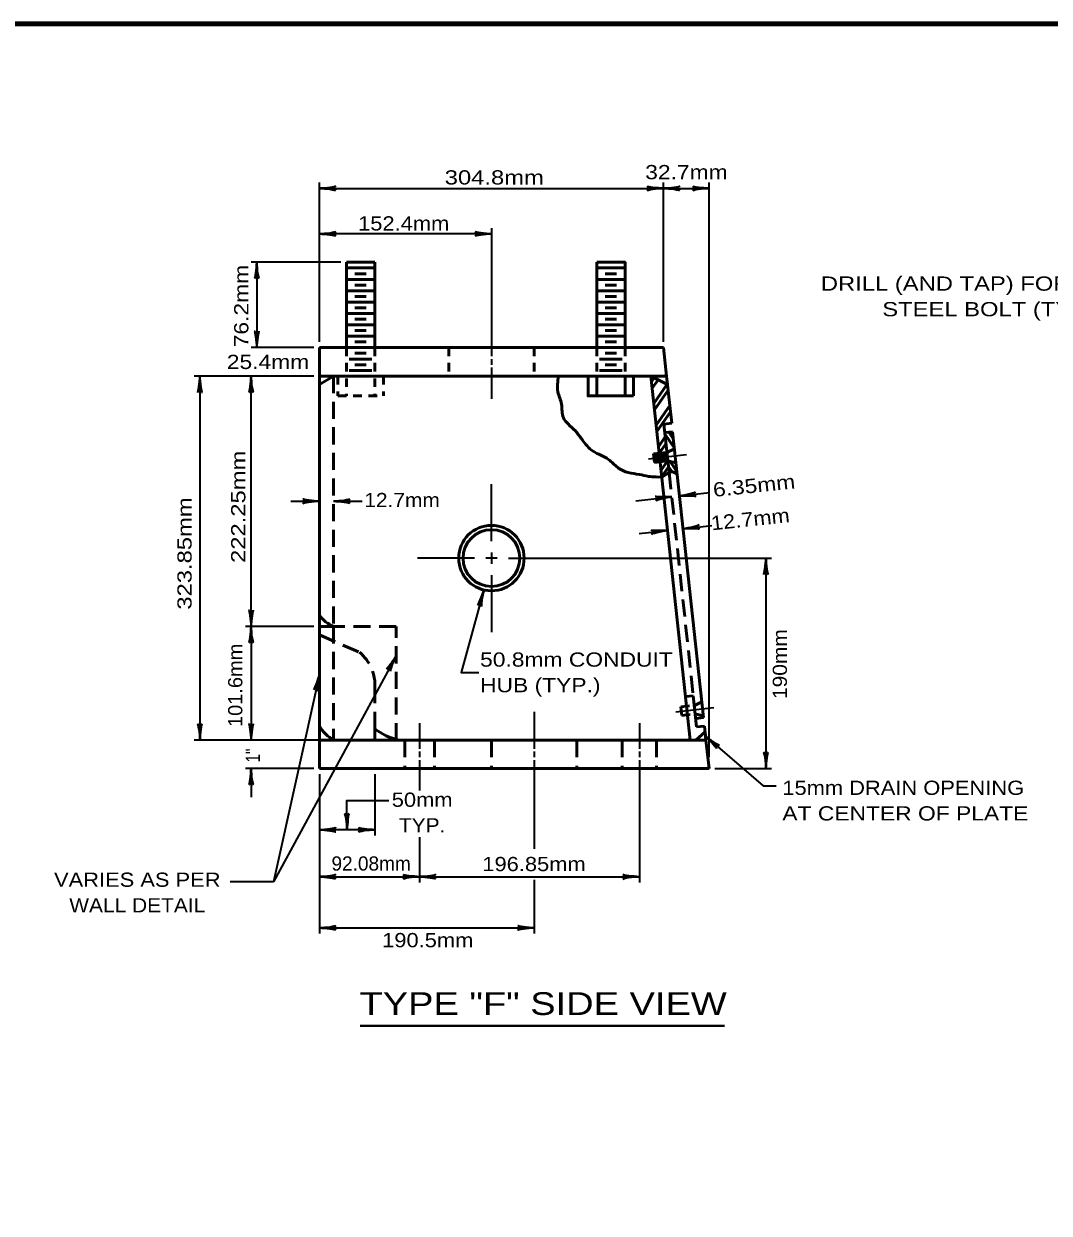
# Model space of a CAD drawing. Extents: x -40 to 816, y -10 to 535.
# Drawn here: x 186.5 to 402.8, y 277.2 to 528.1 of the extents above; entities that cross this region are included whole.
import ezdxf
from ezdxf.enums import TextEntityAlignment as Align

# ---------------------------------------------------------------- set-up
doc = ezdxf.new("R2010")
doc.units = 0
doc.header["$LTSCALE"] = 1.2
doc.linetypes.add('MEDIUM_DASHED', pattern=[4.5, 3, -1.5])
doc.linetypes.add('SHORT_DASHED', pattern=[2.7, 1.5, -1.2])
doc.layers.add('1', color=7, linetype='Continuous', lineweight=53)

msp = doc.modelspace()

# ---------------------------------------------------------------- linework, layer by layer
at = {"layer": '1', "lineweight": 35}
for p, q in [((248.805, 461.005), (248.805, 494.605)), ((321.405, 461.005), (321.405, 494.605)), ((331.005, 373.405), (331.005, 494.605)), ((285.105, 485.005), (285.105, 458.005)), ((285.105, 483.805), (248.805, 483.805)), ((253.305, 477.805), (234.405, 477.805)), ((235.605, 477.805), (235.605, 459.805)), ((247.605, 459.805), (234.405, 459.805)), ((285.105, 457.405), (285.105, 456.205)), ((285.105, 455.605), (285.105, 449.005)), ((247.605, 453.805), (222.405, 453.805)), ((223.605, 453.805), (223.605, 377.005)), ((234.405, 401.005), (234.405, 453.805)), ((318.205, 436.369), (326.258, 437.239)), ((285.105, 419.005), (285.105, 431.005)), ((324.787, 428.521), (331.207, 429.215)), ((242.805, 427.405), (248.805, 427.405)), ((251.805, 427.405), (257.805, 427.405)), ((315.541, 427.522), (323.146, 428.344)), ((325.534, 421.606), (331.616, 422.263)), ((316.288, 420.606), (322.253, 421.251)), ((285.105, 416.605), (285.105, 414.205)), ((281.505, 415.405), (269.505, 415.405)), ((286.305, 415.405), (283.905, 415.405)), ((288.705, 415.405), (344.204, 415.405)), ((343.005, 415.405), (343.005, 371.005)), ((285.105, 411.805), (285.105, 399.805)), ((247.605, 401.005), (233.205, 401.005)), ((234.405, 401.005), (234.405, 377.005)), ((265.005, 394.816), (239.107, 347.123)), ((248.805, 390.857), (239.107, 347.123)), ((323.979, 383.005), (332.032, 383.875)), ((294.105, 383.005), (294.105, 375.205)), ((269.955, 380.605), (269.955, 375.205)), ((316.305, 380.605), (316.305, 375.205)), ((248.805, 377.005), (222.405, 377.005)), ((269.955, 374.605), (269.955, 373.405)), ((294.105, 374.605), (294.105, 373.405)), ((316.305, 374.605), (316.305, 373.405)), ((269.955, 372.805), (269.955, 366.405)), ((294.105, 372.805), (294.105, 354.088)), ((316.305, 372.805), (316.305, 347.005)), ((247.605, 371.005), (233.205, 371.005)), ((234.405, 371.005), (234.405, 365.005)), ((248.805, 369.805), (248.805, 336.205)), ((260.505, 369.805), (260.505, 356.9)), ((332.205, 371.005), (344.204, 371.005)), ((260.505, 358.1), (248.805, 358.1)), ((269.955, 356.548), (269.955, 347.005)), ((239.107, 347.123), (230.022, 347.123)), ((294.105, 347.525), (294.105, 336.205)), ((248.805, 337.405), (294.105, 337.405))]:
    msp.add_line(p, q, dxfattribs=at)
at = {"layer": '1'}
for p, q in [((254.505, 459.805), (254.505, 477.805)), ((254.505, 477.805), (260.505, 477.805)), ((260.505, 459.805), (260.505, 477.805)), ((307.305, 459.805), (307.305, 477.805)), ((254.505, 476.605), (260.505, 476.605)), ((254.505, 474.205), (260.505, 474.205)), ((256.305, 475.405), (258.705, 475.405)), ((313.305, 476.605), (307.305, 476.605)), ((313.305, 474.205), (307.305, 474.205)), ((311.505, 475.405), (309.105, 475.405)), ((254.505, 471.805), (260.505, 471.805)), ((256.305, 473.005), (258.705, 473.005)), ((313.305, 471.805), (307.305, 471.805)), ((311.505, 473.005), (309.105, 473.005)), ((254.505, 469.405), (260.505, 469.405)), ((256.305, 470.605), (258.705, 470.605)), ((313.305, 469.405), (307.305, 469.405)), ((311.505, 470.605), (309.105, 470.605)), ((254.505, 467.005), (260.505, 467.005)), ((256.305, 468.205), (258.705, 468.205)), ((313.305, 467.005), (307.305, 467.005)), ((311.505, 468.205), (309.105, 468.205)), ((254.505, 464.605), (260.505, 464.605)), ((256.305, 465.805), (258.705, 465.805)), ((313.305, 464.605), (307.305, 464.605)), ((311.505, 465.805), (309.105, 465.805)), ((254.505, 462.205), (260.505, 462.205)), ((256.305, 463.405), (258.705, 463.405)), ((313.305, 462.205), (307.305, 462.205)), ((311.505, 463.405), (309.105, 463.405)), ((248.805, 459.805), (321.405, 459.805)), ((256.305, 461.005), (258.705, 461.005)), ((311.505, 461.005), (309.105, 461.005)), ((255.105, 457.405), (259.905, 457.405)), ((256.305, 458.605), (258.705, 458.605)), ((312.705, 457.405), (307.905, 457.405)), ((311.505, 458.605), (309.105, 458.605)), ((255.105, 455.005), (259.905, 455.005)), ((256.305, 456.205), (258.705, 456.205)), ((312.705, 455.005), (307.905, 455.005)), ((311.505, 456.205), (309.105, 456.205)), ((248.805, 453.805), (248.805, 401.005)), ((307.305, 453.805), (307.305, 449.605)), ((313.305, 453.805), (313.305, 449.605)), ((315.105, 453.805), (315.105, 449.605)), ((318.863, 452.608), (319.44, 453.446)), ((319.012, 451.237), (320.249, 453.033)), ((319.358, 448.036), (322.137, 452.072)), ((322.053, 453.805), (322.247, 452.016)), ((319.506, 446.665), (322.375, 450.831)), ((319.852, 443.465), (322.721, 447.63)), ((320, 442.093), (322.869, 446.259)), ((321.49, 443.664), (323.13, 443.842)), ((321.49, 443.664), (322.586, 433.523)), ((321.683, 441.875), (323.324, 442.052)), ((323.49, 440.511), (322.491, 441.962)), ((323.324, 442.052), (329.84, 381.777)), ((320.346, 438.893), (321.781, 440.976)), ((320.494, 437.522), (321.929, 439.605)), ((323.694, 438.629), (321.725, 441.487)), ((319.301, 437.393), (322.135, 437.699)), ((319.301, 437.393), (319.494, 435.603)), ((319.631, 437.127), (319.76, 435.934)), ((319.898, 437.457), (320.091, 435.668)), ((320.228, 437.191), (320.357, 435.998)), ((320.824, 437.256), (320.953, 436.062)), ((321.091, 437.586), (321.284, 435.797)), ((321.421, 437.32), (321.55, 436.127)), ((321.687, 437.651), (321.88, 435.861)), ((321.942, 437.376), (322.071, 436.183)), ((322.135, 437.699), (323.711, 438.473)), ((319.494, 435.603), (322.328, 435.91)), ((320.88, 433.955), (322.218, 435.898)), ((321.104, 432.692), (322.463, 434.666)), ((322.328, 435.91), (324.033, 435.49)), ((323.192, 433.607), (322.463, 434.666)), ((324.228, 433.69), (322.775, 435.8)), ((251.805, 401.005), (248.805, 401.005)), ((326.043, 386.195), (327.683, 386.372)), ((327.683, 386.372), (328.393, 379.811)), ((328.2, 381.6), (329.84, 381.777)), ((248.805, 377.005), (248.805, 380.005)), ((260.505, 377.005), (260.505, 379.405)), ((260.505, 379.405), (260.505, 377.005)), ((328.393, 379.811), (330.034, 379.988)), ((330.034, 379.988), (330.356, 377.005)), ((248.805, 377.005), (265.579, 377.005)), ((251.805, 377.005), (248.805, 377.005)), ((265.579, 377.005), (260.505, 377.005)), ((265.579, 377.005), (327.037, 377.005)), ((327.037, 377.005), (330.356, 377.005)), ((330.356, 377.005), (331.005, 371.005)), ((248.805, 371.005), (331.005, 371.005))]:
    msp.add_line(p, q, dxfattribs=at)
at = {"layer": '1', "linetype": 'SHORT_DASHED'}
for p, q in [((254.505, 459.805), (254.505, 449.605)), ((260.505, 459.805), (260.505, 449.605)), ((276.105, 459.805), (276.105, 453.805)), ((294.105, 459.805), (294.105, 453.805)), ((307.305, 459.805), (307.305, 453.805)), ((313.305, 459.805), (313.305, 453.805)), ((262.305, 453.805), (262.305, 449.605)), ((325.075, 384.029), (325.269, 382.239)), ((325.269, 382.239), (328.102, 382.545)), ((328.102, 382.545), (329.807, 382.126))]:
    msp.add_line(p, q, dxfattribs=at)
at = {"layer": '1', "linetype": 'MEDIUM_DASHED'}
for p, q in [((322.586, 433.523), (327.684, 386.372)), ((248.805, 399.205), (257.263, 395.54)), ((265.005, 401.005), (251.805, 401.005)), ((265.005, 377.005), (265.005, 401.005)), ((260.505, 379.405), (260.505, 387.99)), ((266.805, 377.005), (266.805, 371.005)), ((273.105, 377.005), (273.105, 371.005)), ((285.105, 377.005), (285.105, 371.005)), ((303.105, 377.005), (303.105, 371.005)), ((312.705, 377.005), (312.705, 371.005)), ((319.905, 377.005), (319.905, 371.005))]:
    msp.add_line(p, q, dxfattribs=at)
at = {"layer": '1', "lineweight": 40}
msp.add_line((257.383, 316.715), (334.272, 316.715), dxfattribs=at)
at = {"layer": '1', "lineweight": 158}
msp.add_lwpolyline([(809.296, 528.117), (17.596, 528.017), (17.696, 2.017)], dxfattribs=at)
at = {"layer": '1', "lineweight": 35}
for points in [[(248.805, 493.405), (321.405, 493.405), (331.005, 493.405)], [(283.522, 408.689), (278.682, 391.296), (282.441, 391.296)], [(330.267, 377.828), (342.399, 367.346), (345.186, 367.346)], [(254.655, 358.1), (254.607, 364.273), (263.485, 364.273)], [(248.805, 348.205), (269.955, 348.205), (316.305, 348.205)]]:
    msp.add_lwpolyline(points, dxfattribs=at)
at = {"layer": '1'}
for points in [[(313.305, 459.805), (313.305, 477.805), (307.305, 477.805)], [(248.805, 459.805), (248.805, 453.805), (322.053, 453.805)], [(321.405, 459.805), (322.053, 453.805), (323.13, 443.842)], [(305.505, 453.805), (305.505, 449.605), (315.105, 449.605)], [(322.247, 452.016), (318.734, 453.805), (322.053, 453.805)], [(318.734, 453.805), (320.494, 437.522), (327.037, 377.005)], [(324.083, 433.203), (324.15, 433.166), (324.292, 433.085)], [(251.805, 401.005), (248.805, 401.005), (248.805, 403.405)], [(248.805, 401.005), (248.805, 377.005), (248.805, 371.005)]]:
    msp.add_lwpolyline(points, dxfattribs=at)
for points in [[(248.805, 453.805), (251.805, 453.805), (248.805, 452.005)], [(328.237, 377.005), (330.162, 378.795), (330.356, 377.005)]]:
    msp.add_lwpolyline(points, close=True, dxfattribs=at)
at = {"layer": '1', "linetype": 'MEDIUM_DASHED'}
msp.add_lwpolyline([(251.805, 453.805), (251.805, 401.005), (251.805, 377.005)], dxfattribs=at)
at = {"layer": '1', "linetype": 'SHORT_DASHED'}
for points in [[(252.705, 453.805), (252.705, 449.605), (262.305, 449.605)], [(325.075, 384.029), (327.909, 384.335), (329.485, 385.109)]]:
    msp.add_lwpolyline(points, dxfattribs=at)
at = {"layer": '1'}
for radius in [6.9, 6]:
    msp.add_circle((285.105, 415.405), radius, dxfattribs=at)
for centre, radius, start, end in [((254.4, 407.325), 6.832, 215.00934, 247.67105), ((256.234, 384.434), 8.649, 210.80234, 239.19766), ((268.532, 389.813), 13.144, 232.35749, 257.01513)]:
    msp.add_arc(centre, radius, start, end, dxfattribs=at)
at = {"layer": '1', "linetype": 'MEDIUM_DASHED'}
msp.add_arc((251.562, 388.621), 8.965, 355.96163, 50.51063, dxfattribs=at)
at = {"layer": '1', "lineweight": 40}
for centre, major_axis, ratio, start_param, end_param in [((250.149, 493.151), (-2.108, 0.211), 0.07063, 3.1407148, 5.41811), ((250.149, 493.151), (-2.108, 0.211), 0.07063, 3.1407148, 5.41811), ((250.114, 493.737), (-2.143, -0.187), 0.122415, 0.8963533, 3.1415927), ((250.114, 493.737), (-2.143, -0.187), 0.122415, 0.8963533, 3.1415927), ((320.095, 493.074), (2.143, 0.187), 0.122415, 0.8963533, 3.1415927), ((320.095, 493.074), (2.143, 0.187), 0.122415, 0.8963533, 3.1415927), ((320.06, 493.659), (2.108, -0.211), 0.07063, 3.1407148, 5.41811), ((320.06, 493.659), (2.108, -0.211), 0.07063, 3.1407148, 5.41811), ((322.749, 493.151), (-2.108, 0.211), 0.07063, 3.1407148, 5.41811), ((322.749, 493.151), (-2.108, 0.211), 0.07063, 3.1407148, 5.41811), ((322.714, 493.737), (-2.143, -0.187), 0.122415, 0.8963533, 3.1415927), ((322.714, 493.737), (-2.143, -0.187), 0.122415, 0.8963533, 3.1415927), ((329.695, 493.074), (2.143, 0.187), 0.122415, 0.8963533, 3.1415927), ((329.66, 493.659), (2.108, -0.211), 0.07063, 3.1407148, 5.41811), ((250.114, 484.137), (-2.143, -0.187), 0.122415, 0.8963533, 3.1415927), ((250.114, 484.137), (-2.143, -0.187), 0.122415, 0.8963533, 3.1415927), ((283.76, 484.059), (2.108, -0.211), 0.07063, 3.1407148, 5.41811), ((283.76, 484.059), (2.108, -0.211), 0.07063, 3.1407148, 5.41811), ((250.149, 483.551), (-2.108, 0.211), 0.07063, 3.1407148, 5.41811), ((250.149, 483.551), (-2.108, 0.211), 0.07063, 3.1407148, 5.41811), ((283.795, 483.474), (2.143, 0.187), 0.122415, 0.8963533, 3.1415927), ((283.795, 483.474), (2.143, 0.187), 0.122415, 0.8963533, 3.1415927), ((235.351, 476.461), (0.211, 2.108), 0.07063, 3.1407148, 5.41811), ((235.936, 476.496), (-0.187, 2.143), 0.122415, 0.8963533, 3.1415927), ((235.273, 461.115), (0.187, -2.143), 0.122415, 0.8963533, 3.1415927), ((235.859, 461.15), (-0.211, -2.108), 0.07063, 3.1407148, 5.41811), ((223.351, 452.461), (0.211, 2.108), 0.07063, 3.1407148, 5.41811), ((223.351, 452.461), (0.211, 2.108), 0.07063, 3.1407148, 5.41811), ((223.936, 452.496), (-0.187, 2.143), 0.122415, 0.8963533, 3.1415927), ((223.936, 452.496), (-0.187, 2.143), 0.122415, 0.8963533, 3.1415927), ((234.151, 452.461), (0.211, 2.108), 0.07063, 3.1407148, 5.41811), ((234.736, 452.496), (-0.187, 2.143), 0.122415, 0.8963533, 3.1415927), ((326.053, 428.992), (-2.11, -0.417), 0.122415, 0.8963533, 3.1415927), ((326.053, 428.992), (-2.11, -0.417), 0.122415, 0.8963533, 3.1415927), ((247.495, 427.074), (2.143, 0.187), 0.122415, 0.8963533, 3.1415927), ((247.46, 427.659), (2.108, -0.211), 0.07063, 3.1407148, 5.41811), ((253.149, 427.151), (-2.108, 0.211), 0.07063, 3.1407148, 5.41811), ((253.114, 427.737), (-2.143, -0.187), 0.122415, 0.8963533, 3.1415927), ((321.782, 428.452), (2.118, 0.017), 0.07063, 3.1407148, 5.41811), ((321.782, 428.452), (2.118, 0.017), 0.07063, 3.1407148, 5.41811), ((321.88, 427.874), (2.11, 0.417), 0.122415, 0.8963533, 3.1415927), ((321.88, 427.874), (2.11, 0.417), 0.122415, 0.8963533, 3.1415927), ((326.151, 428.413), (-2.118, -0.017), 0.07063, 3.1407148, 5.41811), ((326.151, 428.413), (-2.118, -0.017), 0.07063, 3.1407148, 5.41811), ((326.8, 422.076), (-2.11, -0.417), 0.122415, 0.8963533, 3.1415927), ((326.8, 422.076), (-2.11, -0.417), 0.122415, 0.8963533, 3.1415927), ((326.898, 421.498), (-2.118, -0.017), 0.07063, 3.1407148, 5.41811), ((326.898, 421.498), (-2.118, -0.017), 0.07063, 3.1407148, 5.41811), ((320.889, 421.359), (2.118, 0.017), 0.07063, 3.1407148, 5.41811), ((320.889, 421.359), (2.118, 0.017), 0.07063, 3.1407148, 5.41811), ((320.987, 420.781), (2.11, 0.417), 0.122415, 0.8963533, 3.1415927), ((320.987, 420.781), (2.11, 0.417), 0.122415, 0.8963533, 3.1415927), ((342.751, 414.061), (0.211, 2.108), 0.07063, 3.1407148, 5.41811), ((343.336, 414.096), (-0.187, 2.143), 0.122415, 0.8963533, 3.1415927), ((282.917, 407.462), (-0.768, -1.974), 0.07063, 6.2823074, 8.5597026), ((283.49, 407.339), (0.394, 2.115), 0.122415, 0.8963533, 3.1415927), ((234.073, 402.315), (0.187, -2.143), 0.122415, 0.8963533, 3.1415927), ((234.659, 402.35), (-0.211, -2.108), 0.07063, 3.1407148, 5.41811), ((234.151, 399.661), (0.211, 2.108), 0.07063, 3.1407148, 5.41811), ((234.736, 399.696), (-0.187, 2.143), 0.122415, 0.8963533, 3.1415927), ((264.14, 393.755), (-1.191, -1.752), 0.07063, 6.2823074, 8.5597026), ((264.671, 393.507), (0.858, 1.973), 0.122415, 0.8963533, 3.1415927), ((248.266, 389.599), (-0.662, -2.012), 0.07063, 6.2823074, 8.5597026), ((248.266, 389.599), (-0.662, -2.012), 0.07063, 6.2823074, 8.5597026), ((248.845, 389.506), (0.281, 2.133), 0.122415, 0.8963533, 3.1415927), ((248.845, 389.506), (0.281, 2.133), 0.122415, 0.8963533, 3.1415927), ((223.273, 378.315), (0.187, -2.143), 0.122415, 0.8963533, 3.1415927), ((223.859, 378.35), (-0.211, -2.108), 0.07063, 3.1407148, 5.41811), ((234.073, 378.315), (0.187, -2.143), 0.122415, 0.8963533, 3.1415927), ((234.659, 378.35), (-0.211, -2.108), 0.07063, 3.1407148, 5.41811), ((331.118, 376.756), (-1.457, 1.537), 0.07063, 3.1407148, 5.41811), ((331.475, 377.222), (-1.744, 1.259), 0.122415, 0.8963533, 3.1415927), ((342.673, 372.315), (0.187, -2.143), 0.122415, 0.8963533, 3.1415927), ((343.258, 372.35), (-0.211, -2.108), 0.07063, 3.1407148, 5.41811), ((234.151, 369.661), (0.211, 2.108), 0.07063, 3.1407148, 5.41811), ((234.736, 369.696), (-0.187, 2.143), 0.122415, 0.8963533, 3.1415927), ((254.313, 359.407), (0.204, -2.141), 0.122415, 0.8963533, 3.1415927), ((254.898, 359.446), (-0.195, -2.109), 0.07063, 3.1407148, 5.41811), ((250.149, 357.846), (-2.108, 0.211), 0.07063, 3.1407148, 5.41811), ((250.149, 357.846), (-2.108, 0.211), 0.07063, 3.1407148, 5.41811), ((250.114, 358.431), (-2.143, -0.187), 0.122415, 0.8963533, 3.1415927), ((250.114, 358.431), (-2.143, -0.187), 0.122415, 0.8963533, 3.1415927), ((259.195, 357.768), (2.143, 0.187), 0.122415, 0.8963533, 3.1415927), ((259.16, 358.354), (2.108, -0.211), 0.07063, 3.1407148, 5.41811), ((250.149, 347.951), (-2.108, 0.211), 0.07063, 3.1407148, 5.41811), ((250.149, 347.951), (-2.108, 0.211), 0.07063, 3.1407148, 5.41811), ((250.114, 348.537), (-2.143, -0.187), 0.122415, 0.8963533, 3.1415927), ((250.114, 348.537), (-2.143, -0.187), 0.122415, 0.8963533, 3.1415927), ((268.645, 347.874), (2.143, 0.187), 0.122415, 0.8963533, 3.1415927), ((268.645, 347.874), (2.143, 0.187), 0.122415, 0.8963533, 3.1415927), ((268.61, 348.459), (2.108, -0.211), 0.07063, 3.1407148, 5.41811), ((268.61, 348.459), (2.108, -0.211), 0.07063, 3.1407148, 5.41811), ((271.299, 347.951), (-2.108, 0.211), 0.07063, 3.1407148, 5.41811), ((271.299, 347.951), (-2.108, 0.211), 0.07063, 3.1407148, 5.41811), ((271.264, 348.537), (-2.143, -0.187), 0.122415, 0.8963533, 3.1415927), ((271.264, 348.537), (-2.143, -0.187), 0.122415, 0.8963533, 3.1415927), ((314.995, 347.874), (2.143, 0.187), 0.122415, 0.8963533, 3.1415927), ((314.96, 348.459), (2.108, -0.211), 0.07063, 3.1407148, 5.41811), ((250.149, 337.151), (-2.108, 0.211), 0.07063, 3.1407148, 5.41811), ((250.114, 337.737), (-2.143, -0.187), 0.122415, 0.8963533, 3.1415927), ((292.795, 337.074), (2.143, 0.187), 0.122415, 0.8963533, 3.1415927), ((292.76, 337.659), (2.108, -0.211), 0.07063, 3.1407148, 5.41811)]:
    msp.add_ellipse(centre, major_axis=major_axis, ratio=ratio, start_param=start_param, end_param=end_param, dxfattribs=at)
at = {"layer": '1'}
msp.add_spline([(299.253, 453.805), (299.119, 450.484), (299.879, 447.909), (300.288, 444.984), (301.283, 443.697), (302.803, 442.235), (304.207, 440.421), (306.546, 437.964), (309.822, 436.209), (311.752, 434.512), (313.974, 433.459), (316.313, 433.049), (318.243, 432.64), (319.764, 432.523), (321.752, 432.874), (322.586, 433.523), (323.507, 433.518), (324.15, 433.166)], degree=3, dxfattribs=at)

# ---------------------------------------------------------------- texts
for s, height, width, p in [('304.8mm', 3, 1.25, (285.702, 494.216)), ('32.7mm', 3, 1.2, (326.234, 495.329)), ('152.4mm', 3, 1.15, (266.593, 484.51)), ('DRILL (AND TAP) FOR 25.4mm', 3, 1.25, (390.674, 471.821)), ('STEEL BOLT (TYP.)', 3, 1.25, (390.674, 466.421)), ('25.4mm', 3, 1.2, (237.973, 455.293)), ('12.7mm', 3, 1.1, (266.246, 426.156)), ('50mm', 3, 1.15, (270.484, 362.944)), ('TYP.', 3, 1.1, (270.484, 357.543)), ('196.85mm', 3, 1.15, (294.081, 349.376)), ('VARIES AS PER', 3, 1.15, (210.396, 346.072)), ('WALL DETAIL', 3, 1.1, (210.395, 340.672)), ('190.5mm', 3, 1.15, (271.665, 333.328)), ('TYPE "F" SIDE VIEW', 4.8, 1.25, (296.009, 319.034))]:
    msp.add_text(s, height=height, dxfattribs=dict(at, width=width)).set_placement(p, align=Align.CENTER)
for s, rotation, width, p in [('76.2mm', 90, 1.2, (233.831, 468.566)), ('222.25mm', 90, 1.25, (233.195, 426.226)), ('6.35mm', 6, 1.2, (340.648, 429.212)), ('323.85mm', 90, 1.25, (221.856, 416.377)), ('12.7mm', 6, 1.15, (339.856, 422.131)), ('190mm', 90, 1.1, (347.439, 393.044)), ('101.6mm', 90, 1.05, (232.557, 388.565)), ('1"', 90, 0.8, (236.264, 373.766))]:
    msp.add_text(s, height=3, rotation=rotation, dxfattribs=dict(at, width=width)).set_placement(p, align=Align.CENTER)
for s, width, p in [('50.8mm CONDUIT', 1.2, (282.706, 392.511)), ('HUB (TYP.)', 1.2, (282.706, 387.111)), ('15mm DRAIN OPENING', 1.15, (346.466, 365.459)), ('AT CENTER OF PLATE', 1.2, (346.466, 360.06))]:
    msp.add_text(s, height=3, dxfattribs=dict(at, width=width)).set_placement(p)
msp.add_text('92.08mm', height=3, dxfattribs=at).set_placement((259.726, 349.493), align=Align.CENTER)

doc.saveas('drawing.dxf')
